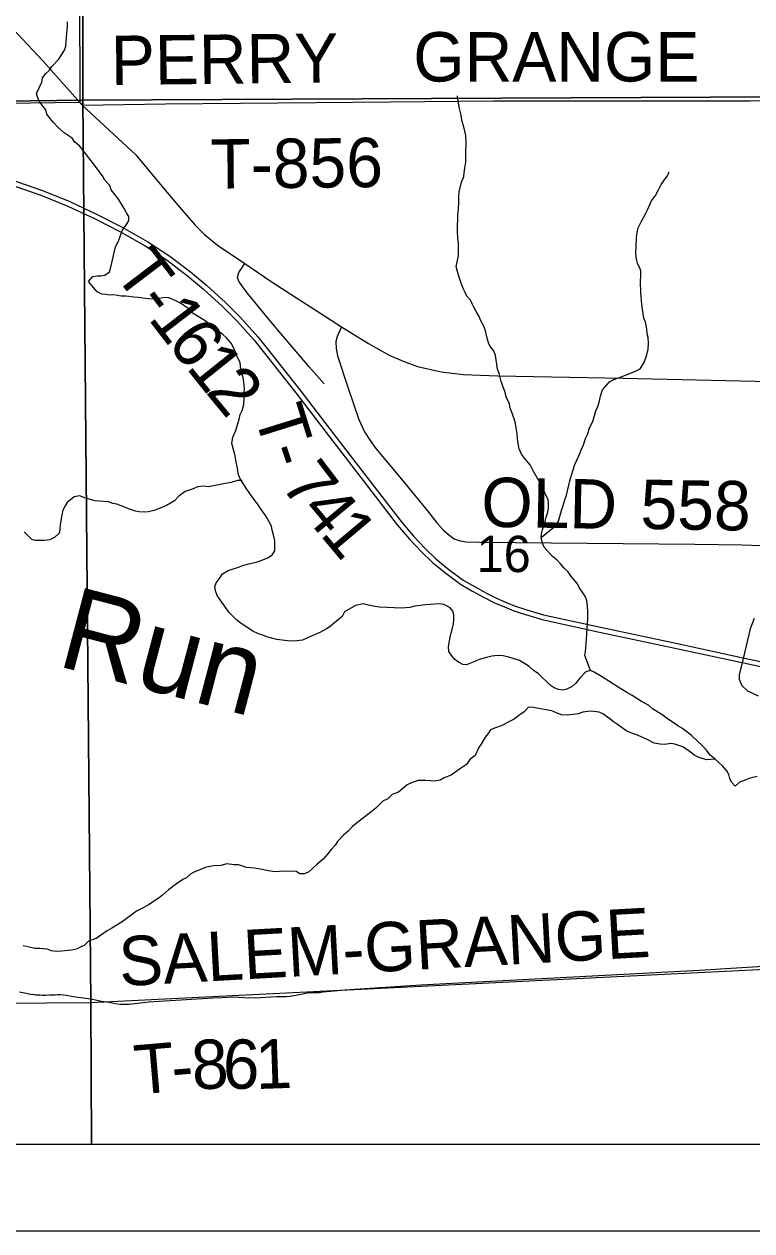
# Model space of a CAD drawing. Extents: x 0 to 34, y 0 to 22.
# Drawn here: x 7.419 to 8.257, y 14 to 15.389 of the extents above; entities that cross this region are included whole.
import ezdxf

# ---------------------------------------------------------------- set-up
doc = ezdxf.new("R2010")
doc.units = 0
for name, color, linetype in [('Default', 7, 'Continuous'), ('GM_X_Minor_River', 7, 'Continuous'), ('GM_X_Minor_River_Text', 7, 'Continuous'), ('GM_X_Rail_Line', 7, 'Continuous'), ('GM_X_Section', 7, 'Continuous'), ('GM_X_Section_Text', 7, 'Continuous'), ('GM_X_State_Route', 7, 'Continuous'), ('GM_X_Township', 7, 'Continuous'), ('GM_X_Township_Road', 7, 'Continuous'), ('GM_X_Township_Road_Text', 7, 'Continuous'), ('SH_Cut_Line', 7, 'Continuous'), ('SH_Data', 7, 'Continuous')]:
    doc.layers.add(name, color=color, linetype=linetype)

msp = doc.modelspace()

# ---------------------------------------------------------------- linework, layer by layer
at = {"layer": 'Default'}
for points in [[(7.4967, 14.1), (8.4613, 14.1), (8.4592, 14.31), (7.496, 14.2624)], [(6.527, 14.1), (7.4967, 14.1), (7.496, 14.2624), (6.5252, 14.2552)]]:
    msp.add_lwpolyline(points, close=True, dxfattribs=at)
at = {"layer": 'GM_X_Minor_River'}
for points in [[(7.673, 14.9698), (7.6721, 14.9774), (7.6713, 14.9819), (7.6688, 14.9921), (7.6679, 14.9993), (7.6631, 15.0095), (7.6615, 15.0148), (7.6575, 15.0219), (7.6521, 15.0282), (7.6479, 15.032), (7.6371, 15.0397), (7.6301, 15.046), (7.6259, 15.049), (7.619, 15.053), (7.614, 15.0563), (7.6094, 15.0611), (7.6005, 15.0674), (7.5933, 15.0711), (7.586, 15.0743), (7.5811, 15.0746), (7.5769, 15.0737), (7.5697, 15.0728), (7.5629, 15.073), (7.5587, 15.0733), (7.5508, 15.0747), (7.5454, 15.0749), (7.5367, 15.0759), (7.531, 15.0761), (7.5227, 15.0775), (7.5181, 15.0774), (7.5132, 15.078), (7.5086, 15.0783), (7.5033, 15.0812), (7.4974, 15.0883), (7.4932, 15.0928), (7.4984, 15.0986), (7.5033, 15.0995), (7.5074, 15.0996), (7.5123, 15.1001), (7.5176, 15.104), (7.519, 15.1093), (7.5245, 15.133), (7.5275, 15.1388), (7.5296, 15.1438), (7.5321, 15.1518), (7.5373, 15.1584), (7.5398, 15.1627), (7.5397, 15.1676), (7.537, 15.1721), (7.5346, 15.177), (7.5279, 15.1879), (7.5194, 15.1983), (7.5181, 15.2036), (7.512, 15.2096), (7.5096, 15.2145), (7.4963, 15.232), (7.4874, 15.2436), (7.4831, 15.2492), (7.4777, 15.2533), (7.4746, 15.2578), (7.4654, 15.2641), (7.458, 15.2707), (7.453, 15.276), (7.4491, 15.2808), (7.4456, 15.2857), (7.4444, 15.2906), (7.437, 15.2999), (7.435, 15.3045), (7.4337, 15.3094), (7.4395, 15.3224), (7.4406, 15.3274), (7.4443, 15.3324), (7.4483, 15.3363), (7.4513, 15.3406), (7.4594, 15.3491), (7.4657, 15.3591), (7.4671, 15.3637), (7.4677, 15.3698), (7.468, 15.3744), (7.4693, 15.387), (7.4692, 15.3919)], [(7.9201, 15.2936), (7.9188, 15.3011), (7.918, 15.3053), (7.918, 15.3069)], [(8.0711, 14.6451), (8.0647, 14.6625), (8.0654, 14.6671), (8.0666, 14.6808), (8.0674, 14.6937), (8.068, 14.7044), (8.0682, 14.712), (8.0677, 14.7196), (8.0668, 14.7253), (8.0652, 14.7306), (8.0624, 14.7347), (8.0581, 14.7407), (8.0562, 14.7448), (8.0519, 14.7497), (8.0484, 14.7541), (8.0449, 14.759), (8.041, 14.7631), (8.0367, 14.768), (8.0325, 14.7724), (8.0275, 14.7765), (8.0178, 14.7873), (8.0158, 14.7918), (8.0145, 14.7983), (8.0148, 14.8025), (8.0158, 14.807), (8.0173, 14.8116), (8.019, 14.817), (8.0201, 14.8216), (8.0219, 14.8273), (8.0229, 14.8323), (8.0228, 14.8372), (8.0223, 14.8418), (8.0203, 14.8463), (8.0176, 14.8523), (8.0109, 14.8651), (8.0053, 14.8749), (8.0018, 14.882), (7.9952, 14.8895), (7.9917, 14.894), (7.9889, 14.9004), (7.9876, 14.9083), (7.9867, 14.9174), (7.9857, 14.9246), (7.9849, 14.9296), (7.9833, 14.9348), (7.9797, 14.9443), (7.9784, 14.9484), (7.978, 14.9526), (7.9744, 14.959), (7.9724, 14.9665), (7.9684, 14.9779), (7.9659, 14.9869), (7.9643, 14.9922), (7.9634, 14.9979), (7.9625, 15.0025), (7.9617, 15.0078), (7.96, 15.013), (7.9558, 15.0183), (7.9538, 15.0224), (7.9522, 15.0277), (7.9505, 15.036), (7.9485, 15.0417), (7.9449, 15.0477), (7.9429, 15.0526), (7.9394, 15.0586), (7.9374, 15.0627), (7.9351, 15.0672), (7.9331, 15.0714), (7.9288, 15.0762), (7.9268, 15.0804), (7.9248, 15.0849), (7.9224, 15.0909), (7.9208, 15.0958), (7.9192, 15.1004), (7.918, 15.1045), (7.9167, 15.1102), (7.9181, 15.1171), (7.9191, 15.1228), (7.9194, 15.1274), (7.9192, 15.1372), (7.9183, 15.1425), (7.9182, 15.1513), (7.9185, 15.1703), (7.9192, 15.1757), (7.9197, 15.1848), (7.9196, 15.1913), (7.9199, 15.1962), (7.9227, 15.2073), (7.9252, 15.2138), (7.9259, 15.218), (7.9265, 15.2233), (7.9275, 15.2302), (7.9277, 15.2371), (7.9276, 15.2447), (7.9282, 15.2489), (7.9282, 15.2534), (7.9276, 15.261), (7.9255, 15.2709), (7.9235, 15.2773), (7.9218, 15.286), (7.9201, 15.2936)], [(8.0145, 14.7983), (8.0309, 14.8116), (8.0342, 14.817), (8.0377, 14.8292), (8.0395, 14.8338), (8.0416, 14.8415), (8.0434, 14.8468), (8.0473, 14.8636), (8.0494, 14.8701), (8.0512, 14.8763), (8.0533, 14.8824), (8.0558, 14.8882), (8.058, 14.8932), (8.0605, 14.8993), (8.0631, 14.9051), (8.0656, 14.9123), (8.0681, 14.9177), (8.0702, 14.9246), (8.0739, 14.9319), (8.0749, 14.9361), (8.0774, 14.9442), (8.0796, 14.9492), (8.081, 14.9541), (8.0827, 14.961), (8.0849, 14.9683), (8.093, 14.9776), (8.0982, 14.98), (8.1046, 14.9824), (8.1152, 14.9865), (8.1238, 14.9901), (8.1283, 14.9925), (8.1331, 14.9998), (8.1359, 15.0086), (8.1377, 15.0151), (8.1379, 15.0216), (8.1374, 15.0284), (8.1365, 15.0329), (8.1361, 15.0386), (8.1344, 15.0462), (8.1324, 15.0507), (8.1302, 15.0663), (8.1296, 15.0758), (8.1291, 15.0807), (8.1289, 15.0921), (8.1291, 15.1005), (8.129, 15.1054), (8.1274, 15.1096), (8.1254, 15.1137), (8.1242, 15.119), (8.1233, 15.1247), (8.1238, 15.1338), (8.124, 15.1437), (8.1247, 15.1494), (8.1261, 15.1548), (8.1293, 15.1617), (8.1344, 15.1709), (8.1366, 15.1755), (8.1413, 15.1859), (8.1461, 15.1921), (8.1498, 15.1994), (8.1527, 15.2048), (8.156, 15.2098), (8.1597, 15.2148), (8.1619, 15.2191)], [(8.0344, 14.6234), (8.0295, 14.6252), (8.0249, 14.6281), (8.0113, 14.6411), (8.0052, 14.6456), (8.0006, 14.6496), (7.9952, 14.6533), (7.9894, 14.6566), (7.9772, 14.6605), (7.9707, 14.6619), (7.9647, 14.6622), (7.9575, 14.6616), (7.9515, 14.66), (7.9432, 14.6579), (7.936, 14.6547), (7.9285, 14.6518), (7.9244, 14.6521), (7.9194, 14.6547), (7.9151, 14.6576), (7.9116, 14.6621), (7.9081, 14.667), (7.9076, 14.6727), (7.9097, 14.6834), (7.9107, 14.6883), (7.9118, 14.6925), (7.9135, 14.699), (7.9138, 14.7044), (7.9137, 14.7093), (7.9129, 14.7135), (7.9094, 14.7176), (7.9025, 14.7212), (7.8971, 14.7219), (7.8813, 14.7208), (7.8688, 14.719), (7.8631, 14.7177), (7.8537, 14.7167), (7.8366, 14.7175), (7.8279, 14.7181), (7.8211, 14.719), (7.8157, 14.7204), (7.81, 14.7218), (7.8006, 14.7201), (7.7882, 14.7126), (7.7853, 14.7072), (7.779, 14.7021), (7.7715, 14.6959), (7.7674, 14.6931), (7.7596, 14.6888), (7.7453, 14.6828), (7.7397, 14.68), (7.7298, 14.679), (7.7223, 14.6792), (7.7101, 14.6808), (7.6987, 14.684), (7.6941, 14.6858), (7.6891, 14.6872), (7.6826, 14.6905), (7.6692, 14.6993), (7.6638, 14.7034), (7.6553, 14.7119), (7.6467, 14.7239), (7.6416, 14.7314), (7.6396, 14.7367), (7.6387, 14.742), (7.6405, 14.7462), (7.645, 14.752), (7.6475, 14.7563), (7.6543, 14.7602), (7.6671, 14.7643), (7.6712, 14.7659), (7.6765, 14.7675), (7.6863, 14.77), (7.6908, 14.7713), (7.6998, 14.7749), (7.7047, 14.7781), (7.708, 14.7827), (7.7077, 14.7945), (7.7065, 14.8013), (7.7048, 14.8066), (7.704, 14.8111), (7.6992, 14.8205), (7.6965, 14.8246), (7.6914, 14.8318), (7.6879, 14.837), (7.6836, 14.8422), (7.6758, 14.8539), (7.668, 14.8658), (7.6656, 14.8715), (7.6651, 14.8757), (7.6634, 14.8855), (7.6617, 14.8938), (7.6584, 14.9063), (7.6594, 14.9136), (7.663, 14.9216), (7.6669, 14.9343), (7.668, 14.94), (7.6701, 14.9446), (7.6723, 14.9515), (7.6725, 14.9587), (7.6727, 14.9648), (7.673, 14.9698)], [(7.6703, 14.864), (7.665, 14.8639), (7.6575, 14.8614), (7.6469, 14.8597), (7.6416, 14.8584), (7.6371, 14.8576), (7.6314, 14.8567), (7.6261, 14.8573), (7.6189, 14.8564), (7.6137, 14.8544), (7.6046, 14.8511), (7.5972, 14.846), (7.5924, 14.8406), (7.583, 14.8351), (7.5778, 14.8327), (7.5729, 14.8307), (7.5687, 14.8294), (7.5623, 14.8278), (7.5582, 14.8273), (7.5517, 14.8279), (7.5475, 14.8286), (7.5395, 14.8311), (7.5342, 14.8336), (7.5258, 14.8365), (7.5212, 14.8375), (7.5163, 14.8393), (7.5007, 14.8405), (7.4931, 14.8426), (7.4881, 14.8444), (7.4835, 14.8462), (7.4767, 14.8449), (7.4689, 14.8386), (7.466, 14.834), (7.4638, 14.8298), (7.4624, 14.8221), (7.4614, 14.8179), (7.4607, 14.813), (7.4605, 14.8076), (7.4598, 14.8034), (7.4542, 14.7984), (7.449, 14.7956), (7.4429, 14.7947), (7.4365, 14.7946), (7.4323, 14.7948), (7.4281, 14.7959), (7.4235, 14.8004), (7.4192, 14.8048)], [(8.2631, 14.5231), (8.2548, 14.5211), (8.2506, 14.5198), (8.2424, 14.5162), (8.2375, 14.5119), (8.2336, 14.5164), (8.2317, 14.5209), (8.2304, 14.5255), (8.2281, 14.5296), (8.223, 14.5352), (8.2145, 14.543), (8.2091, 14.5478), (8.2045, 14.5534), (8.1994, 14.559), (8.1948, 14.5635), (8.1875, 14.5701), (8.1771, 14.5783), (8.1717, 14.5816), (8.1675, 14.5845), (8.1598, 14.5893), (8.1532, 14.5945), (8.1425, 14.6011), (8.1379, 14.6052), (8.1298, 14.6095), (8.1191, 14.6165), (8.1129, 14.6198), (8.1079, 14.6228), (8.1029, 14.6261), (8.0922, 14.6327), (8.0838, 14.6382), (8.0753, 14.6433), (8.0711, 14.6451), (8.0658, 14.6435), (8.0584, 14.6361), (8.054, 14.6303), (8.0499, 14.6268), (8.0439, 14.6236), (8.0394, 14.6224), (8.0344, 14.6234)], [(8.2145, 14.543), (8.2047, 14.5424), (8.1963, 14.5449), (8.1913, 14.5474), (8.1848, 14.5522), (8.1775, 14.5574), (8.1683, 14.5602), (8.1638, 14.5609), (8.1566, 14.5599), (8.1513, 14.5602), (8.1444, 14.5616), (8.1364, 14.5656), (8.1253, 14.5707), (8.1177, 14.5732), (8.1119, 14.5761), (8.1023, 14.5831), (8.0977, 14.586), (8.0935, 14.5893), (8.0854, 14.5952), (8.0812, 14.5971), (8.0751, 14.5981), (8.0709, 14.5984), (8.0623, 14.597), (8.057, 14.5954), (8.0445, 14.5936), (8.0377, 14.5942), (8.0335, 14.5956), (8.0266, 14.5985), (8.0201, 14.5999), (8.0114, 14.6012), (8.0038, 14.6029), (7.9996, 14.6025), (7.9948, 14.5974), (7.9888, 14.5935), (7.9832, 14.5892), (7.9787, 14.5868), (7.9682, 14.5816), (7.9607, 14.5788), (7.9562, 14.5768), (7.9533, 14.5725), (7.95, 14.5683), (7.9456, 14.561), (7.9426, 14.5563), (7.9383, 14.5471), (7.9323, 14.5428), (7.9286, 14.537), (7.9204, 14.5315), (7.9107, 14.5248), (7.9028, 14.5216), (7.898, 14.5188), (7.8919, 14.5179), (7.8874, 14.5182), (7.8813, 14.5185), (7.873, 14.5183), (7.8658, 14.5162), (7.8602, 14.5134), (7.8501, 14.5052), (7.843, 14.5024), (7.8378, 14.4973), (7.8322, 14.4946), (7.824, 14.4868), (7.8165, 14.4805), (7.8035, 14.4707), (7.7972, 14.4656), (7.7923, 14.4602), (7.7868, 14.4555), (7.7801, 14.4481), (7.7771, 14.4439), (7.7731, 14.4396), (7.7686, 14.4338), (7.7635, 14.428), (7.7564, 14.4221), (7.7467, 14.4128), (7.7415, 14.4112), (7.7365, 14.4111), (7.7323, 14.4136), (7.7206, 14.4141), (7.7134, 14.4136), (7.7081, 14.4135), (7.7005, 14.4144), (7.6913, 14.4165), (7.6845, 14.4175), (7.6754, 14.4184), (7.6659, 14.4213), (7.6609, 14.4215), (7.6526, 14.4225), (7.6458, 14.4208), (7.6375, 14.4203), (7.6329, 14.4194), (7.628, 14.4182), (7.6156, 14.4133), (7.6111, 14.4109), (7.6063, 14.4066), (7.6018, 14.4046), (7.5947, 14.3995), (7.5854, 14.3925), (7.5787, 14.3866), (7.5746, 14.3835), (7.5626, 14.3753), (7.557, 14.3721), (7.5488, 14.3681)], [(7.5488, 14.3681), (7.532, 14.3559), (7.5204, 14.3485), (7.5148, 14.3453), (7.5021, 14.3367), (7.4934, 14.3334), (7.4882, 14.3284), (7.4837, 14.3267), (7.4796, 14.3244), (7.4739, 14.3231), (7.4698, 14.3226), (7.4622, 14.3221), (7.4566, 14.3216), (7.4509, 14.3222), (7.4459, 14.3244), (7.4375, 14.325), (7.4315, 14.3252), (7.425, 14.3266), (7.4182, 14.3283)]]:
    msp.add_lwpolyline(points, dxfattribs=at)
at = {"layer": 'GM_X_Rail_Line'}
msp.add_lwpolyline([(5.5619, 14.1), (8.9, 14.1), (8.9, 17.3138), (8.2882, 17.3064), (7.4754, 17.3006), (7.4757, 17.0495), (7.4723, 16.4951), (7.4818, 15.827), (7.482, 15.8179), (7.4834, 15.2992), (7.3416, 15.297), (6.5709, 15.2859), (6.3575, 15.2833), (5.5569, 15.2761), (5.5579, 15.2049), (5.5588, 15.1747), (5.5581, 14.9676), (5.5583, 14.9347), (5.5595, 14.6439), (5.5615, 14.2414), (5.5608, 14.205)], close=True, dxfattribs=at)
for points in [[(7.3998, 15.2059), (7.4385, 15.1923), (7.4695, 15.1798), (7.5009, 15.1652), (7.5295, 15.1505), (7.5586, 15.134), (7.5838, 15.1175), (7.6073, 15.0996), (7.6258, 15.0842), (7.6473, 15.0645), (7.6642, 15.0475), (7.684, 15.0256), (7.6946, 15.0125), (7.7176, 14.9832), (7.732, 14.9646), (7.7708, 14.9142), (7.807, 14.8674), (7.8488, 14.813), (7.8633, 14.7961), (7.8765, 14.7818), (7.8895, 14.7694), (7.9048, 14.757), (7.9217, 14.7445), (7.9355, 14.7364), (7.9486, 14.7293), (7.96, 14.7235), (7.9721, 14.7183), (7.9829, 14.714), (7.9963, 14.7095), (8.0157, 14.704), (8.0814, 14.6894), (8.1648, 14.6717), (8.2439, 14.6546), (8.3733, 14.6268)], [(7.4016, 15.2113), (7.4405, 15.1976), (7.4718, 15.1849), (7.5034, 15.1702), (7.5322, 15.1555), (7.5616, 15.1388), (7.587, 15.1221), (7.6108, 15.104), (7.6295, 15.0884), (7.6512, 15.0686), (7.6683, 15.0514), (7.6883, 15.0292), (7.699, 15.016), (7.722, 14.9867), (7.7365, 14.9681), (7.7752, 14.9177), (7.8115, 14.8709), (7.8532, 14.8166), (7.8675, 14.7998), (7.8805, 14.7858), (7.8932, 14.7736), (7.9082, 14.7615), (7.9248, 14.7492), (7.9383, 14.7413), (7.9513, 14.7343), (7.9624, 14.7286), (7.9742, 14.7235), (7.9849, 14.7192), (7.998, 14.7149), (8.0171, 14.7094), (8.0826, 14.6949), (8.166, 14.6772), (8.245, 14.6601), (8.3745, 14.6323)]]:
    msp.add_lwpolyline(points, dxfattribs=at)
at = {"layer": 'GM_X_Section'}
for points in [[(7.4857, 16.2946), (8.4434, 16.3129), (8.4501, 15.3065), (7.4868, 15.3017)], [(6.5053, 16.2508), (7.4857, 16.2946), (7.4868, 15.3017), (6.5184, 15.2893)], [(6.5184, 15.2893), (7.4868, 15.3017), (7.496, 14.2624), (6.5252, 14.2552)], [(7.4868, 15.3017), (8.4501, 15.3065), (8.4592, 14.31), (7.496, 14.2624)]]:
    msp.add_lwpolyline(points, close=True, dxfattribs=at)
at = {"layer": 'GM_X_State_Route'}
for points in [[(6.6453, 16.2527), (6.7342, 16.135), (6.8206, 16.019), (6.9337, 15.8667), (7.0828, 15.6666), (7.0979, 15.6472), (7.1155, 15.6342), (7.2286, 15.5659), (7.2423, 15.557), (7.2588, 15.5429), (7.2823, 15.5175), (7.371, 15.4215), (7.4407, 15.3469), (7.4836, 15.2986), (7.4861, 15.2958)], [(7.4861, 15.2958), (7.548, 15.2387), (7.5856, 15.1934)], [(7.5856, 15.1934), (7.601, 15.1749), (7.6163, 15.1579), (7.627, 15.1472), (7.6419, 15.1348), (7.6734, 15.1138), (7.7038, 15.093), (7.7844, 15.0406)], [(7.7844, 15.0406), (7.8155, 15.0217), (7.8394, 15.0082), (7.8556, 15.0011), (7.8722, 14.9952), (7.8993, 14.9889), (7.9247, 14.9859), (7.9647, 14.9845), (8.1088, 14.9815), (8.2775, 14.978), (8.3183, 14.9772), (8.4559, 14.9747), (8.5031, 14.9735), (8.5319, 14.9737), (8.5511, 14.9742), (8.5747, 14.975), (8.6032, 14.9777), (8.6416, 14.9824), (8.6555, 14.9854), (8.743, 15.0009), (8.8016, 15.0236), (8.8553, 15.0495), (8.9, 15.0742)]]:
    msp.add_lwpolyline(points, dxfattribs=at)
at = {"layer": 'GM_X_Township'}
msp.add_lwpolyline([(7.482, 15.8179), (7.4834, 15.2992), (7.3416, 15.297), (6.5709, 15.2859), (6.3575, 15.2833), (5.5569, 15.2761), (5.5579, 15.2049), (4.0847, 15.1965), (3.5411, 15.1931), (3.5298, 15.9318)], dxfattribs=at)
at = {"layer": 'GM_X_Township_Road'}
for points in [[(7.4861, 15.2958), (7.5821, 15.2975), (7.841, 15.2997), (7.9594, 15.3011), (8.255, 15.301), (8.4418, 15.3026)], [(7.7645, 14.9753), (7.7475, 14.9948), (7.704, 15.0456), (7.6761, 15.08), (7.6669, 15.0924), (7.665, 15.0974), (7.6665, 15.1033), (7.6734, 15.1138)], [(7.7844, 15.0406), (7.7797, 15.0297), (7.7782, 15.0237), (7.7785, 15.0159), (7.7799, 15.0073), (7.7917, 14.9714), (7.8045, 14.934), (7.811, 14.92), (7.8175, 14.9099), (7.8242, 14.9007), (7.8516, 14.8676)], [(7.8516, 14.8676), (7.8835, 14.8291), (7.8944, 14.8153), (7.9017, 14.8072), (7.9076, 14.8016), (7.9144, 14.7968), (7.9211, 14.7943), (7.9281, 14.7934), (7.9436, 14.7928), (8.1912, 14.7905), (8.2458, 14.7899), (8.2672, 14.7891)], [(8.2596, 14.7049), (8.255, 14.6932), (8.2465, 14.6573), (8.2421, 14.6403), (8.2423, 14.6352), (8.2453, 14.6279), (8.2518, 14.6219), (8.264, 14.6159)], [(7.414, 14.2752), (7.4197, 14.2742), (7.4251, 14.2727), (7.429, 14.2722), (7.4301, 14.2725), (7.4314, 14.2722), (7.4327, 14.2719), (7.434, 14.2717), (7.4353, 14.2717), (7.4367, 14.2717), (7.4379, 14.2719), (7.4401, 14.2715), (7.4441, 14.2715), (7.4488, 14.2719), (7.4547, 14.2716), (7.4578, 14.272), (7.4611, 14.2721), (7.4675, 14.2715), (7.4757, 14.27), (7.4961, 14.267), (7.5085, 14.2645), (7.5173, 14.2632), (7.5241, 14.2618), (7.53, 14.2611), (7.5351, 14.2609), (7.5397, 14.2609), (7.5623, 14.2636), (7.6367, 14.2681), (7.6473, 14.2687), (7.6597, 14.2693), (7.6722, 14.2687), (7.6858, 14.2682), (7.7093, 14.27), (7.7175, 14.2697), (7.7214, 14.2699), (7.7252, 14.2703), (7.7319, 14.2715), (7.7474, 14.2744), (7.7587, 14.2746), (7.7633, 14.2752), (7.7678, 14.2755), (7.7885, 14.2774), (7.8757, 14.2831), (8.0948, 14.2947), (8.1967, 14.3), (8.2878, 14.3059)]]:
    msp.add_lwpolyline(points, dxfattribs=at)
at = {"layer": 'SH_Cut_Line'}
msp.add_lwpolyline([(2.1, 17.2107), (2.1, 14.1), (8.9, 14.1)], dxfattribs=at)
at = {"layer": 'SH_Data'}
for p, q in [((2.1, 14.1), (8.9, 14.1)), ((2, 14), (9, 14))]:
    msp.add_line(p, q, dxfattribs=at)

# ---------------------------------------------------------------- texts
at = {"layer": 'GM_X_Minor_River_Text'}
msp.add_text('Run', height=0.09473, rotation=345.2784, dxfattribs=at).set_placement((7.4552, 14.651))
at = {"layer": 'GM_X_Section_Text'}
msp.add_text('16', height=0.04186, rotation=0, dxfattribs=at).set_placement((7.9401, 14.7584))
at = {"layer": 'GM_X_Township_Road_Text'}
for s, height, rotation, p in [('GRANGE', 0.05682, 0, (7.8672, 15.3232)), ('PERRY', 0.05682, 0.6391, (7.5194, 15.3191)), ('T-856', 0.05682, 0.5614, (7.634, 15.1998)), ('T', 0.0568, 307.2333, (7.5212, 15.1029)), ('-', 0.0568, 307.2811, (7.5469, 15.069)), ('1', 0.0568, 307.479, (7.5612, 15.0503)), ('6', 0.0568, 307.9794, (7.5828, 15.0221)), ('1', 0.0568, 308.6654, (7.6048, 14.9939)), ('2', 0.0568, 309.5415, (7.6273, 14.9658)), ('T', 0.0568, 287.329, (7.6835, 14.9405)), ('-', 0.0568, 288.5854, (7.6965, 14.8986)), ('7', 0.0568, 307.2525, (7.7134, 14.8588)), ('OLD', 0.05682, 358.9942, (7.9451, 14.8107)), ('558', 0.05682, 359.0838, (8.1284, 14.8082)), ('4', 0.0568, 309.8358, (7.7363, 14.8287)), ('1', 0.0568, 310.0312, (7.7589, 14.8017)), ('SALEM-GRANGE', 0.056818, 3.1756, (7.5298, 14.2816)), ('T', 0.0568, 4.9046, (7.5484, 14.1568)), ('8', 0.0568, 3.3429, (7.6136, 14.1623)), ('6', 0.0568, 358.173, (7.6472, 14.1643)), ('1', 0.0568, 2.0261, (7.6863, 14.1632)), ('-', 0.0568, 4.5867, (7.5907, 14.1604))]:
    msp.add_text(s, height=height, rotation=rotation, dxfattribs=at).set_placement(p)

doc.saveas('drawing.dxf')
